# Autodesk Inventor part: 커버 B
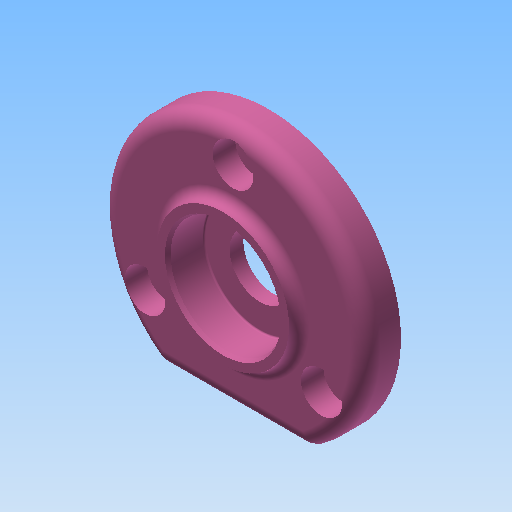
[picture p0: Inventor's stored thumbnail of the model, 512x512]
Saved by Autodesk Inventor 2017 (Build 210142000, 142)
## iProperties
Created: 2020-04
Part Number: 커버 B
Material: 알루미늄 6061
Document SubType Name: Modeling
Designer: mduedu
Density: 2.71 g/cm^3
Mass: 33.6775 g
Surface Area: 62.2844 cm^2
Volume: 12.4271 cm^3
Appearance: 분홍색
Author: mduedu
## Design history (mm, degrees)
sketch "스케치1"
  geometry: C1 r 26 at (0, 0); 1 further point
  constraints: 1 centre point, 1 coincident
  dimensions: "d0" = 52 diameter of C1
extrude "돌출1" new body sketch "스케치1" distance "d1" = 7; taper "d2" = 0 deg
sketch "스케치2"
  geometry: L1 (-14.62, -21.5)-(14.62, -21.5); A1 r 26 centre (0, 0) between (-14.62, -21.5) and (14.62, -21.5) reference; 1 further point
  constraints: 2 end point, 2 point on circle, 1 horizontal
  dimensions: "d3" = 21.5 distance from line of L1 point (0, 0)
extrude "돌출2" cut sketch "스케치2" stored distance "d4" = 7; taper "d5" = 0 deg
sketch "스케치6"
  geometry: C1 r 13 at (0, 0); 1 further point
  constraints: 1 centre point, 1 coincident
  dimensions: "d29" = 26 diameter of C1
extrude "돌출5" join sketch "스케치6" distance "d30" = 2; taper "d31" = 0 deg
fillet "모깎기1" dims "d6" = 3
fillet "모깎기2" dims "d7" = 3
fillet "모깎기4" dims "d33" = 2
sketch "스케치3" dims "d8" = 40
  geometry: 3 further points
  constraints: 2 vertical alignment, 1 coincident, 2 other
hole "구멍1" sketch "스케치3" at (0, 20) diameter "d9" = 4.5; stored, may be unused: countersink angle "d13" = 90 deg, drill point angle "d15" = 118 deg; dims "d10" = 6, "d11" = 8, "d12" = 4.4, "d14" = 8
sketch "스케치4"
  geometry: C1 r 14 at (0, 0); 1 further point
  constraints: 1 centre point, 1 coincident
  dimensions: "d19" = 28 diameter of C1
extrude "돌출3" join sketch "스케치4" distance "d20" = 4; taper "d21" = 0 deg
sketch "스케치5"
  geometry: C1 r 12 at (0, 0); 1 further point
  constraints: 1 centre point, 1 coincident
  dimensions: "d22" = 24 diameter of C1
extrude "돌출4" cut sketch "스케치5" distance "d23" = 3; taper "d24" = 0 deg
fillet "모깎기3" dims "d25" = 3
chamfer "모따기1" distance "d26" = 0.5; stored, may be unused: second distance "d27" = 2, angle "d28" = 45 deg
sketch "스케치7"
  geometry: 2 further points
  constraints: 1 coincident
hole "구멍2" sketch "스케치7" at (0, 0) diameter "d34" = 12; stored, may be unused: countersink angle "d38" = 90 deg, drill point angle "d40" = 118 deg; dims "d35" = 6, "d36" = 22, "d37" = 7.3, "d39" = 8
fillet "모깎기5" dims "d41" = 0.3
chamfer "모따기2" distance "d42" = 0.7; stored, may be unused: second distance "d43" = 2, angle "d44" = 30 deg
node "솔리드1"
pattern_circular "원형 패턴1" dims angle "d17" = 360 deg
node "투영된 루프1"
